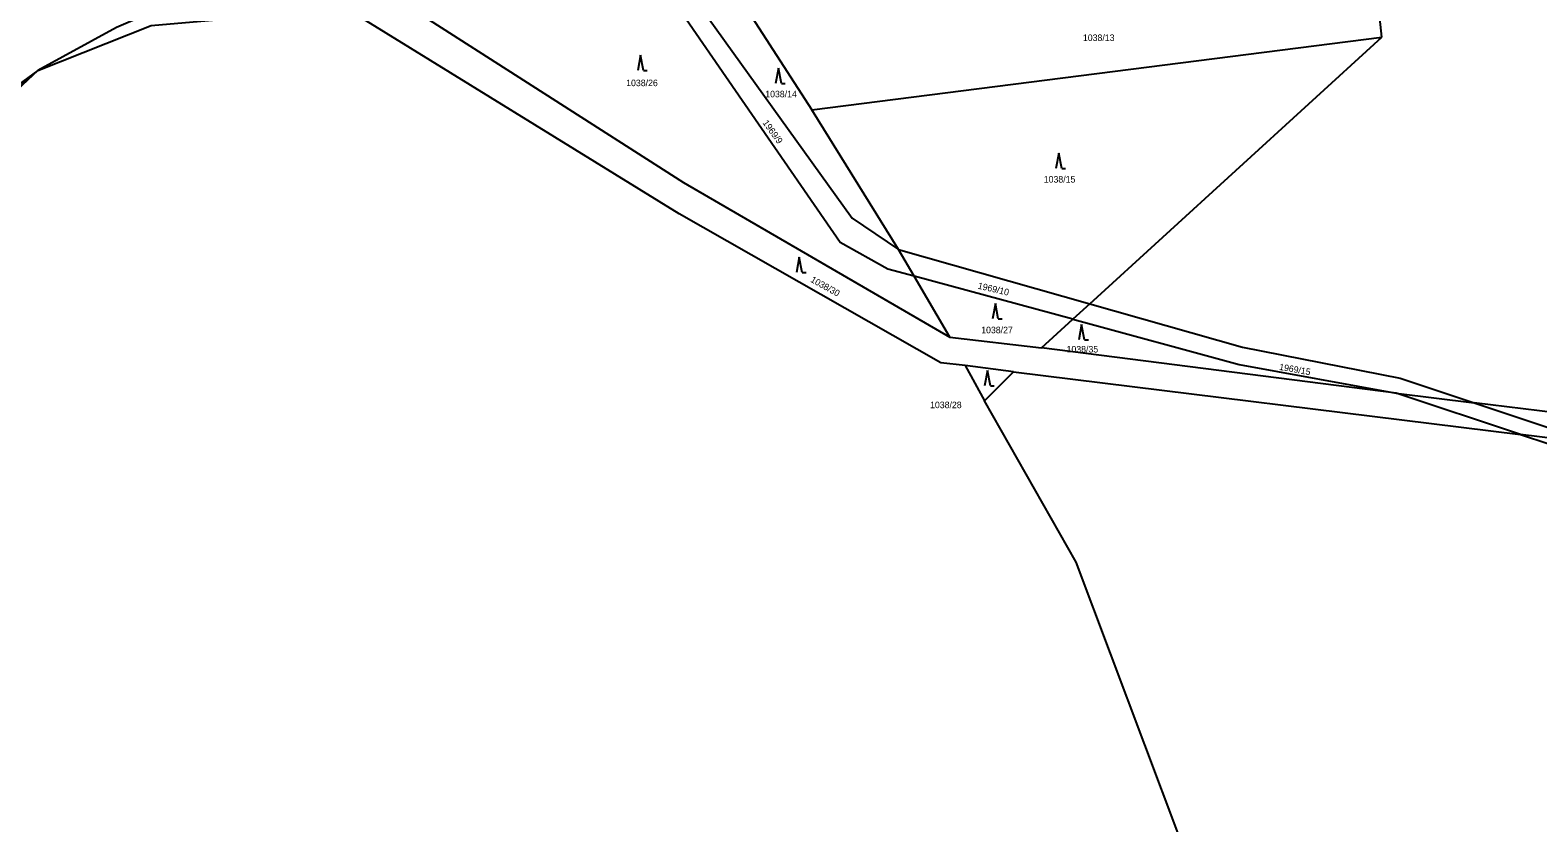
# Model space of a CAD drawing. Extents: x -794765 to -785424, y -1118958 to -1108731.
# Drawn here: x -787061.6 to -786669.6, y -1115978.1 to -1115772 of the extents above; entities that cross this region are included whole.
import ezdxf

# ---------------------------------------------------------------- set-up
doc = ezdxf.new("R2010")
doc.units = 0
for name, color, linetype in [('Level 66', 7, 'Continuous'), ('Level 75', 7, 'Continuous'), ('Level 76', 7, 'Continuous')]:
    doc.layers.add(name, color=color, linetype=linetype)

msp = doc.modelspace()

# ---------------------------------------------------------------- linework, layer by layer
at = {"layer": 'Level 66'}
for p, q in [((-786902.88, -1115778.43), (-786903.63, -1115782.43)), ((-786902.13, -1115782.43), (-786902.88, -1115778.43)), ((-786902.13, -1115782.43), (-786901.13, -1115782.43)), ((-786867.03, -1115781.8), (-786867.78, -1115785.8)), ((-786866.28, -1115785.8), (-786867.03, -1115781.8)), ((-786866.28, -1115785.8), (-786865.28, -1115785.8)), ((-786794.15, -1115803.94), (-786794.9, -1115807.94)), ((-786793.4, -1115807.94), (-786794.15, -1115803.94)), ((-786793.4, -1115807.94), (-786792.4, -1115807.94)), ((-786861.62, -1115830.97), (-786862.37, -1115834.97)), ((-786860.87, -1115834.97), (-786861.62, -1115830.97)), ((-786860.87, -1115834.97), (-786859.87, -1115834.97)), ((-786810.65, -1115843.05), (-786811.4, -1115847.05)), ((-786809.9, -1115847.05), (-786810.65, -1115843.05)), ((-786809.9, -1115847.05), (-786808.9, -1115847.05)), ((-786788.21, -1115848.46), (-786788.96, -1115852.46)), ((-786787.46, -1115852.46), (-786788.21, -1115848.46)), ((-786787.46, -1115852.46), (-786786.46, -1115852.46)), ((-786812.69, -1115860.45), (-786813.44, -1115864.45)), ((-786811.94, -1115864.45), (-786812.69, -1115860.45)), ((-786811.94, -1115864.45), (-786810.94, -1115864.45))]:
    msp.add_line(p, q, dxfattribs=at)
at = {"layer": 'Level 75'}
for p, q in [((-786710.19, -1115773.76), (-786712.15, -1115754.3)), ((-786875.79, -1115765.76), (-786858.38, -1115792.69)), ((-786858.38, -1115792.69), (-786710.19, -1115773.76)), ((-786786.09, -1115843.1), (-786710.19, -1115773.76)), ((-787059.63, -1115782.48), (-787201.76, -1115914.44)), ((-787059.63, -1115782.48), (-787151.42, -1115849.12)), ((-786835.82, -1115828.99), (-786858.38, -1115792.69)), ((-786835.82, -1115828.99), (-786786.09, -1115843.1)), ((-786831.78, -1115835.92), (-786835.82, -1115828.99)), ((-786822.51, -1115851.81), (-786831.78, -1115835.92)), ((-786790.51, -1115847.13), (-786831.78, -1115835.92)), ((-786786.09, -1115843.1), (-786790.51, -1115847.13)), ((-786798.67, -1115854.59), (-786790.51, -1115847.13)), ((-786822.51, -1115851.81), (-786798.67, -1115854.59)), ((-786706.44, -1115866.37), (-786798.67, -1115854.59)), ((-786818.52, -1115859.15), (-786813.47, -1115868.32)), ((-786805.96, -1115860.8), (-786818.52, -1115859.15)), ((-786813.47, -1115868.32), (-786805.96, -1115860.8)), ((-786805.96, -1115860.8), (-786674.07, -1115877.11)), ((-786706.44, -1115866.37), (-786686.12, -1115868.87)), ((-786674.07, -1115877.11), (-786706.44, -1115866.37)), ((-786617.46, -1115877.32), (-786686.12, -1115868.87)), ((-786634.53, -1115882), (-786674.07, -1115877.11))]:
    msp.add_line(p, q, dxfattribs=at)
for points in [[(-786831.78, -1115835.92), (-786838.58, -1115834.07), (-786850.97, -1115827.21), (-786896.92, -1115760.48)], [(-786891.5, -1115760.08), (-786847.84, -1115820.86), (-786835.82, -1115828.99)], [(-787020.77, -1115763.28), (-787039.17, -1115771.28), (-787059.63, -1115782.48)], [(-787059.63, -1115782.48), (-787030.16, -1115770.72), (-786979.45, -1115766.29)], [(-786818.52, -1115859.15), (-786824.82, -1115858.48), (-786892.84, -1115819.73), (-786979.45, -1115766.29)], [(-786964.37, -1115765.14), (-786891.74, -1115811.54), (-786822.51, -1115851.81)], [(-787196.06, -1115906.75), (-787129.19, -1115844.27), (-787059.63, -1115782.48)], [(-786786.09, -1115843.1), (-786746.36, -1115854.37), (-786705.38, -1115862.41), (-786686.12, -1115868.87)], [(-786790.51, -1115847.13), (-786747.29, -1115858.88), (-786706.44, -1115866.37)], [(-786680.51, -1116204.92), (-786700.72, -1116148.28), (-786724.56, -1116100.33), (-786753.91, -1116005.28), (-786789.6, -1115910.33), (-786813.47, -1115868.32)], [(-786686.12, -1115868.87), (-786666.42, -1115875.48), (-786643.43, -1115878.75), (-786617.46, -1115877.32)], [(-786674.07, -1115877.11), (-786666.75, -1115879.54), (-786643.06, -1115882.39), (-786634.53, -1115882)]]:
    msp.add_lwpolyline(points, dxfattribs=at)

# ---------------------------------------------------------------- texts
at = {"layer": 'Level 76'}
for s, p in [('1038/13', (-786787.88, -1115774.78)), ('1038/26', (-786906.63, -1115786.52)), ('1038/14', (-786870.47, -1115789.42)), ('1038/15', (-786798.06, -1115811.59)), ('1038/27', (-786814.32, -1115850.77)), ('1038/35', (-786792.13, -1115855.77)), ('1038/28', (-786827.62, -1115870.25))]:
    msp.add_text(s, height=1.7, dxfattribs=at).set_placement(p)
for s, rotation, p in [('1969/9', 306, (-786871.25, -1115796.07)), ('1038/30', 331, (-786858.86, -1115837.32)), ('1969/10', 347, (-786815.32, -1115839.16)), ('1969/15', 350, (-786736.95, -1115860.28))]:
    msp.add_text(s, height=1.7, rotation=rotation, dxfattribs=at).set_placement(p)

doc.saveas('drawing.dxf')
